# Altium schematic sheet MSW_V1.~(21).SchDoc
size B; Organization: ORGANIZATION; Address1: ADDRESS 1; Address2: ADDRESS 2; Address3: ADDRESS 3; Address4: ADDRESS 4; Revision: -; SheetNumber: 1; SheetTotal: 1; ENG_APP_DATE: --/--/--; DSN_APP_DATE: --/--/--; CHK_APP_DATE: --/--/--
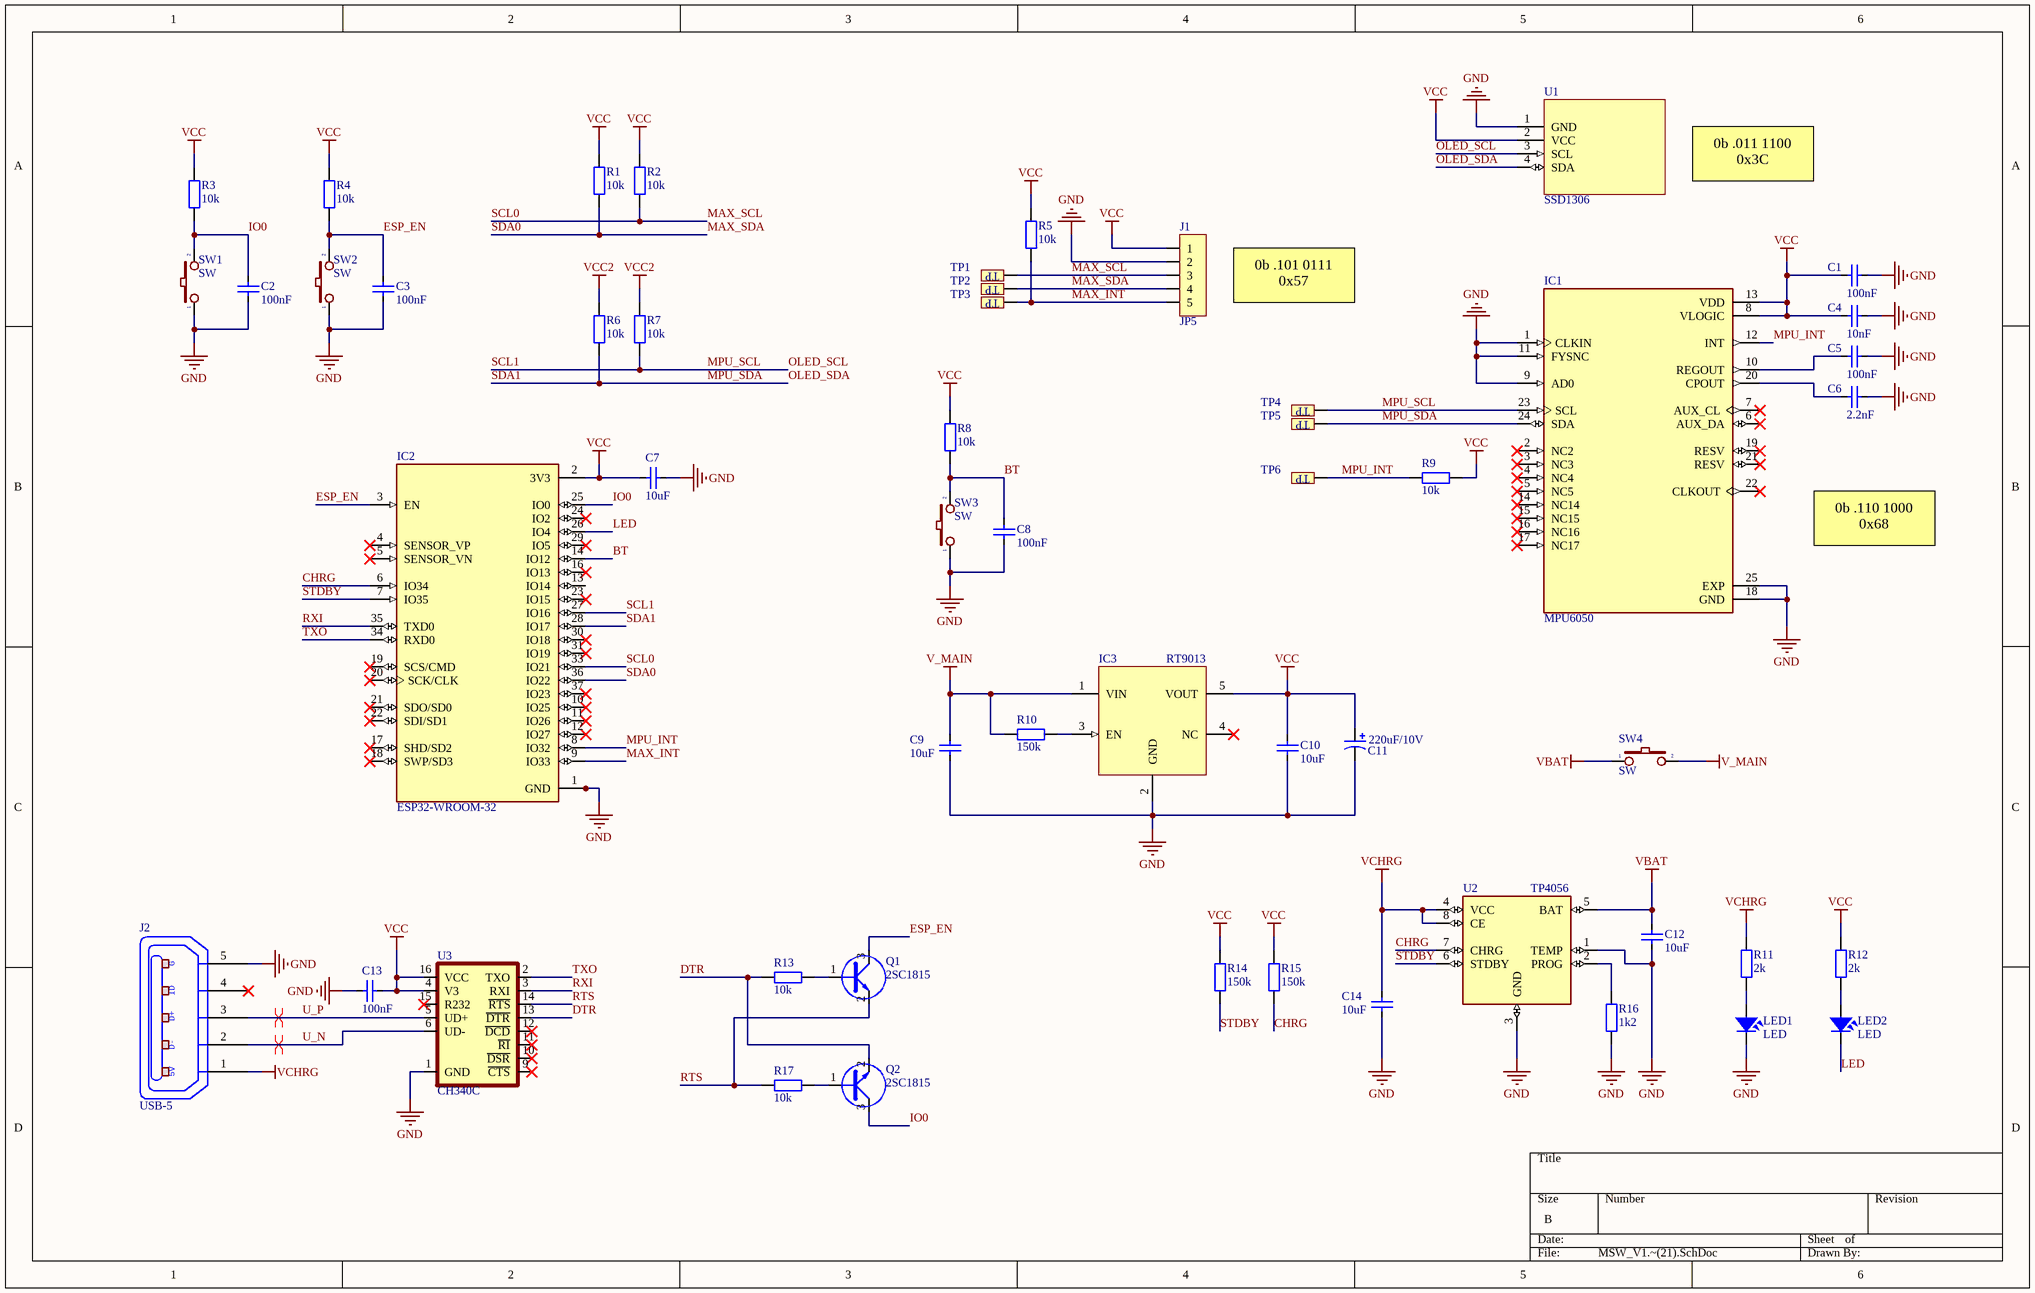
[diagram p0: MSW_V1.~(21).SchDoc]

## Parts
C1  100nF  [CAP_0603]
C2  100nF  [CAP_0603]
C3  100nF  [CAP_0603]
C4  10nF  [CAP_0603]
C5  100nF  [CAP_0603]
C6  2.2nF  [CAP_0603]
C7  10uF  [CAP_0603]
C8  100nF  [CAP_0603]
C9  10uF  [CAP_0603]
C10  10uF  [CAP_0603]
C11  220uF/10V  [CAP_7343]
C12  10uF  [CAP_0603]
C13  100nF  [CAP_0603]
C14  10uF  [CAP_0603]
IC1  MPU6050  [QFN24]
IC2  ESP32-WROOM-32  [MODULE_ESP32-WROOM-32]
IC3  RT9013  [SOT23-5]
J1  JP5  [Header5 - TH - 1.25MM]
J2  USB-5  [USB-M1]
LED1  LED  [LED-0805-Red]
LED2  LED  [LED-1206-Blue]
Q1  2SC1815  [SOT23D]
Q2  2SC1815  [SOT23D]
R1  10k  [RES-SMD-0603]
R2  10k  [RES-SMD-0603]
R3  10k  [RES-SMD-0603]
R4  10k  [RES-SMD-0603]
R5  10k  [RES-SMD-0603]
R6  10k  [RES-SMD-0603]
R7  10k  [RES-SMD-0603]
R8  10k  [RES-SMD-0603]
R9  10k  [RES-SMD-0603]
R10  150k  [RES-SMD-0603]
R11  2k  [RES-SMD-0603]
R12  2k  [RES-SMD-0603]
R13  10k  [RES-SMD-0603]
R14  150k  [RES-SMD-0603]
R15  150k  [RES-SMD-0603]
R16  1k2  [RES-SMD-0603]
R17  10k  [RES-SMD-0603]
SW1  SW  [SW 3x2x4]
SW2  SW  [SW 3x2x4]
SW3  SW  [SW 3x2x4]
SW4  SW  [SW102_SIDE]
TP1  TP  [TP_SMD]  (value not drawn)
TP2  TP  [TP_SMD]  (value not drawn)
TP3  TP  [TP_SMD]  (value not drawn)
TP4  TP  [TP_SMD]  (value not drawn)
TP5  TP  [TP_SMD]  (value not drawn)
TP6  TP  [TP_SMD]  (value not drawn)
U1  SSD1306  [OLED 1.3 SSD1306 PRETTY NON POLE]
U2  TP4056  [TP4056]
U3  CH340C  [SOP-16]

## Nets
GND: C1.1 C2.2 C3.2 C4.1 C5.1 C6.1 C7.2 C8.2 C9.1 C10.1 C11.2 C12.1 C13.1 C14.1 IC1.1(CLKIN) IC1.9(AD0) IC1.11(FYSNC) IC1.18(GND) IC1.25(EXP) IC2.1(GND) IC2.15(GND) IC2.38(GND) IC2.39_1(GND) IC2.39_2(GND) IC2.39_3(GND) IC2.39_4(GND) IC2.39_5(GND) IC2.39_6(GND) IC2.39_7(GND) IC2.39_8(GND) IC2.39_9(GND) IC2.39_10(GND) IC2.39_11(GND) IC2.39_12(GND) IC2.39_13(GND) IC2.39_14(GND) IC2.39_15(GND) IC2.39_16(GND) IC2.39_17(GND) IC2.39_18(GND) IC2.39_19(GND) IC2.39_20(GND) IC2.39_21(GND) IC3.2(GND) J1.2 J2.5(P5) LED1.2 R16.1 SW1.1 SW2.1 SW3.1 U1.1(GND) U2.1(TEMP) U2.3(GND) U3.1(GND)
V_MAIN: C9.2 IC3.1(VIN) R10.1 SW4.2
VBAT: C12.2 SW4.1 U2.5(BAT)
VCC: C1.2 C4.2 C7.1 C10.2 C11.1 C13.2 IC1.8(VLOGIC) IC1.13(VDD) IC2.2(3V3) IC3.5(VOUT) J1.1 R1.2 R2.2 R3.2 R4.2 R5.1 R8.2 R9.1 R12.2 R14.1 R15.1 U1.2(VCC) U3.4(V3) U3.16(VCC)
VCC2: R6.2 R7.2
VCHRG: C14.2 J2.1(P1) R11.2 U2.4(VCC) U2.8(CE)
BT: C8.1 IC2.14(IO12) R8.1 SW3.2
CHRG: IC2.6(IO34) R15.2 U2.7(CHRG)
DTR: Q2.2(E) R13.2 U3.13(~{DTR})
ESP_EN: C3.1 IC2.3(EN) Q1.3(C) R4.1 SW2.2
IO0: C2.1 IC2.25(IO0) Q2.3(C) R3.1 SW1.2
LED: IC2.26(IO4) LED2.2
MAX_INT: IC2.9(IO33) J1.5 R5.2 TP3.1
MAX_SCL: IC2.33(IO21) J1.3 R2.1 TP1.1  [also labelled SCL0]
MAX_SDA: IC2.36(IO22) J1.4 R1.1 TP2.1  [also labelled SDA0]
MPU_INT: IC1.12(INT) IC2.8(IO32) R9.2 TP6.1
MPU_SCL: IC1.23(SCL) IC2.27(IO16) R7.1 TP4.1 U1.3(SCL)  [also labelled OLED_SCL, SCL1]
MPU_SDA: IC1.24(SDA) IC2.28(IO17) R6.1 TP5.1 U1.4(SDA)  [also labelled OLED_SDA, SDA1]
RTS: Q1.2(E) R17.2 U3.14(~{RTS})
RXI: IC2.35(TXD0) U3.3(RXI)
STDBY: IC2.7(IO35) R14.2 U2.6(STDBY)
TXO: IC2.34(RXD0) U3.2(TXO)
U_N: J2.2(P2) U3.6(UD-)
U_P: J2.3(P3) U3.5(UD+)
NetC5_2: C5.2 IC1.10(REGOUT)
NetC6_2: C6.2 IC1.20(CPOUT)
NetIC3_3: IC3.3(EN) R10.2
NetLED1_1: LED1.1 R11.1
NetLED2_1: LED2.1 R12.1
NetQ1_1: Q1.1(B) R13.1
NetQ2_1: Q2.1(B) R17.1
NetR16_2: R16.2 U2.2(PROG)

Not connected (* = marked no-connect by the designer): IC1 2(NC2)* 3(NC3)* 4(NC4)* 5(NC5)* 6(AUX_DA)* 7(AUX_CL)* 14(NC14)* 15(NC15)* 16(NC16)* 17(NC17)* 19(RESV)* 21(RESV)* 22(CLKOUT)*; IC2 4(SENSOR_VP)* 5(SENSOR_VN)* 10(IO25)* 11(IO26)* 12(IO27)* 13(IO14) 16(IO13)* 17(SHD/SD2)* 18(SWP/SD3)* 19(SCS/CMD)* 20(SCK/CLK)* 21(SDO/SD0)* 22(SDI/SD1)* 23(IO15)* 24(IO2)* 29(IO5)* 30(IO18)* 31(IO19)* 37(IO23)*; IC3 4(NC)*; J2 4(P4)*; U3 9(~{CTS})* 10(~{DSR})* 11(~{RI})* 12(~{DCD})* 15(R232)*

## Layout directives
differential pair: U_N, U_P

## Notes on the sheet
- 0b .011 1100
  0x3C
- 0b .101 0111
  0x57
- 0b .110 1000
  0x68

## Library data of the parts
C1-C10 C12-C14 = CapSMD: Capacitor; Value: 33p
C11 = CAP_TAN_SMD: Polazied Tantalum Capacitor
IC1 = MPU6050_Chip: 3-axis gyroscope, 3-axis accelerometer
IC2 = ESP32-WROOM-32: Bluetooth, WiFi Transceiver Module 2.4GHz ~ 2.5GHz Surface Mount; MF: Espressif Systems
IC3 = RT9013: RT9013-33GB IC REG LINEAR 3.3V 500mA SOT23-5
J1 = JP5x1: WR-PHD 2.54 mm Angled Socket Header; Manufacturer: W¨¹rth Elektronik eiSos GmbH; partNo: 613005143121; ComponentLink1 Description: Manufacturer; ComponentLink2 Description: Datasheet; NoPins: 05
J2 = USB-5: Manufacturer: FCI; Manufacturer Part Number: 10118193-0001LF; Connector Type: USB - micro B; Number of Contacts: 5; Gender: Receptacle; Specifications: USB 2.0; .Creator: MM; .Checked PCB: RF
LED1 LED2 = LED: LED Single colour Green and Red; Value: LED 3 ly Single Colour
Q1 Q2 = C1815: NPN 600mW, ECB; Value: C1815
R1-R17 = Resistor - SMD: Resistor SMD; Manufacturer: Generic Components; Class: Passive
SW1-SW4 = SW2: Switch button 2 pin; Value: SW chip 2 pin
TP1-TP6 = TP: CONNECT 1
U1 = OLED 1.3 SSD1306: OLED Display 1.3" SSD1306
U2 = TP4056: Complete single cell Li-Ion battery with a constant current / constant voltage linear charger
U3 = CH340C: USB to serial chip CH340; MF: WCH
